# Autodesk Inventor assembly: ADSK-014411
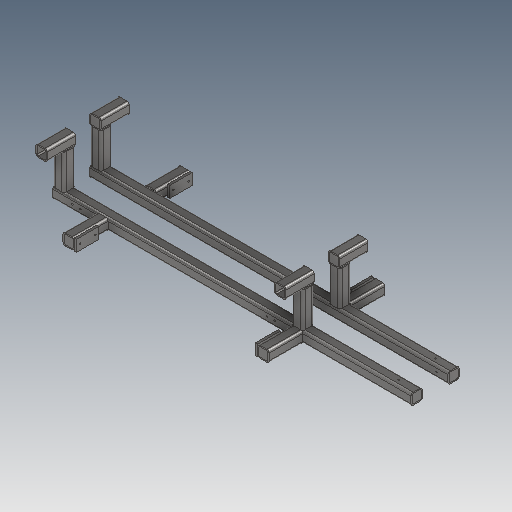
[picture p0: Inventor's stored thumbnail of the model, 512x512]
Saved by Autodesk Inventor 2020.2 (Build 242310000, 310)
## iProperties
_FrameDoc: Frame Assembly
_Version: 15.0.0
Part Number: ADSK-014411
Description: Phantom-Baugruppe
Document SubType Name: Baugruppe
Designer: lutzd
Mass: 34390.2 g
Surface Area: 17624.2 cm^2
Volume: 4380.92 cm^3
Density: 7.85 g/cm^3
DocNumber: ADSK-014411
Folder: .
Mass: 34,39 kg
Dimensions: 255x514x1590 mm
Title: Gestellbaugruppen
Author: lutzd
Revision Number: -
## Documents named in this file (10)
- D:\07 - DEMODATEN\OTX 2019 - Dataset - UPDATE - Dez2019\Designs\07-Packing machine\500666L\Frame\ADSK-014411.iam
- D:\07 - DEMODATEN\OTX 2019 - Dataset - UPDATE - Dez2019\Designs\07-Packing machine\500666L\Frame\ADSK-014419.ipt
- D:\07 - DEMODATEN\OTX 2019 - Dataset - UPDATE - Dez2019\Designs\07-Packing machine\500666L\Frame\ADSK-014418.ipt
- D:\07 - DEMODATEN\OTX 2019 - Dataset - UPDATE - Dez2019\Designs\07-Packing machine\500666L\Frame\ADSK-014417.ipt
- D:\07 - DEMODATEN\OTX 2019 - Dataset - UPDATE - Dez2019\Designs\07-Packing machine\500666L\Frame\ADSK-014415.ipt
- D:\07 - DEMODATEN\OTX 2019 - Dataset - UPDATE - Dez2019\Designs\07-Packing machine\500666L\Frame\ADSK-014414.ipt
- D:\07 - DEMODATEN\OTX 2019 - Dataset - UPDATE - Dez2019\Designs\07-Packing machine\500666L\Frame\ADSK-014412.ipt
- D:\07 - DEMODATEN\OTX 2019 - Dataset - UPDATE - Dez2019\Designs\07-Packing machine\500666L\Frame\ADSK-014432.ipt
- D:\07 - DEMODATEN\OTX 2019 - Dataset - UPDATE - Dez2019\Designs\07-Packing machine\500666L\Frame\ADSK-014435.ipt
- D:\07 - DEMODATEN\OTX 2019 - Dataset - UPDATE - Dez2019\Designs\07-Packing machine\500666L\Frame\ADSK-014437.ipt
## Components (31 placed, 4 different names)
1. Gestellreferenzmodell
2. DIN 50 x 50 x 5:1
3. DIN 50 x 50 x 5:17
4. DIN 50 x 50 x 5:7
5. DIN 50 x 50 x 5:8
6. DIN 50 x 50 x 5:15
7. DIN 50 x 50 x 5:16
8. DIN 50 x 50 x 5:2
9. DIN 50 x 50 x 5:9
10. DIN 50 x 50 x 5:11
11. DIN 50 x 50 x 5:12
12. DIN 50 x 50 x 5:4
13. DIN 50 x 50 x 5:13
14. DIN 50 x 50 x 5:5
15. DIN 50 x 50 x 5:14
16. DIN 50 x 10:2
17. DIN 50 x 10:3
18. DIN 50 x 10:4
19. DIN 50 x 10:5
20. Gerundete Ecken (mm) 5 x 40 x 40:1
21. Gerundete Ecken (mm) 5 x 40 x 40:2
22. Gerundete Ecken (mm) 5 x 40 x 40:3
23. Gerundete Ecken (mm) 5 x 40 x 40:4
24. Gerundete Ecken (mm) 5 x 40 x 40:5
25. Gerundete Ecken (mm) 5 x 40 x 40:6
26. Gerundete Ecken (mm) 5 x 40 x 40:7
27. Gerundete Ecken (mm) 5 x 40 x 40:8
28. Gerundete Ecken (mm) 5 x 40 x 40:9
29. Gerundete Ecken (mm) 5 x 40 x 40:10
30. Gerundete Ecken (mm) 5 x 40 x 40:11
31. Gerundete Ecken (mm) 5 x 40 x 40:12
